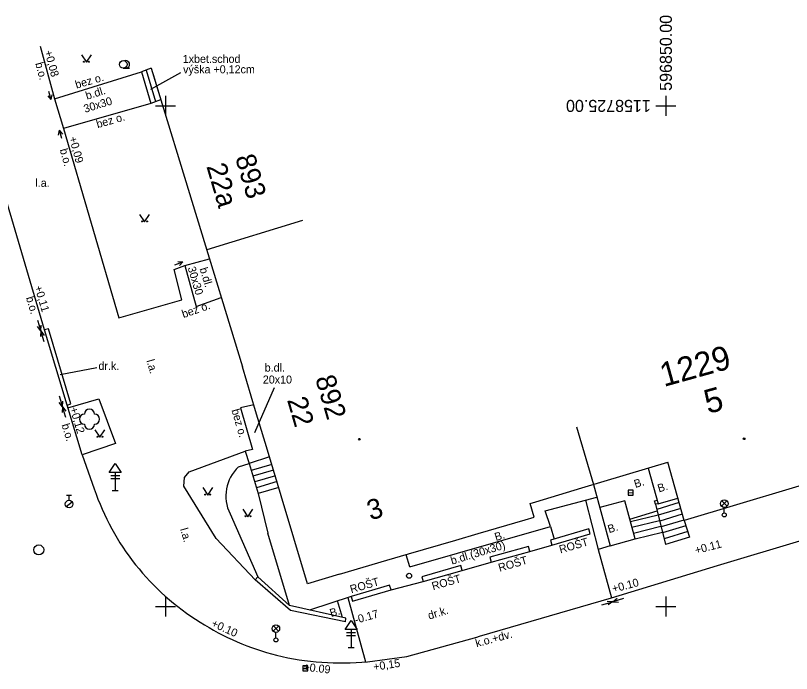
# Model space of a CAD drawing. Extents: x -597333 to -596488, y -1158921 to -1158644.
# Drawn here: x -596882.49 to -596843.72, y -1158753.34 to -1158720.49 of the extents above; entities that cross this region are included whole.
import ezdxf

# ---------------------------------------------------------------- set-up
doc = ezdxf.new("R2010")
doc.units = 0
for name, color, linetype in [('Vrstva 12', 7, 'Continuous'), ('Vrstva 14', 7, 'Continuous'), ('Vrstva 15', 7, 'Continuous'), ('Vrstva 17', 7, 'Continuous'), ('Vrstva 22', 7, 'Continuous'), ('Vrstva 23', 7, 'Continuous'), ('Vrstva 24', 7, 'Continuous'), ('Vrstva 25', 7, 'Continuous'), ('Vrstva 29', 7, 'Continuous'), ('Vrstva 4', 7, 'Continuous'), ('Vrstva 41', 7, 'Continuous'), ('Vrstva 43', 7, 'Continuous'), ('Vrstva 44', 7, 'Continuous'), ('Vrstva 49', 7, 'Continuous'), ('Vrstva 5', 7, 'Continuous'), ('Vrstva 50', 7, 'Continuous'), ('Vrstva 52', 7, 'Continuous'), ('Vrstva 62', 7, 'Continuous'), ('Vrstva 7', 7, 'Continuous')]:
    doc.layers.add(name, color=color, linetype=linetype)

msp = doc.modelspace()

# ---------------------------------------------------------------- linework, layer by layer
at = {"layer": 'Vrstva 12'}
msp.add_line((-596853.61, -1158743.9), (-596852.79, -1158746.96), dxfattribs=at)
at = {"layer": 'Vrstva 14'}
msp.add_line((-596877.11, -1158723.117), (-596876.797, -1158723.117), dxfattribs=at)
for points in [[(-596879.2, -1158722.45), (-596878.95, -1158722.825), (-596878.7, -1158722.45)], [(-596876.293, -1158730.419), (-596876.043, -1158730.794), (-596875.793, -1158730.419)], [(-596878.526, -1158741.168), (-596878.276, -1158741.543), (-596878.026, -1158741.168)], [(-596873.141, -1158744.054), (-596872.891, -1158744.429), (-596872.641, -1158744.054)], [(-596871.131, -1158745.135), (-596870.881, -1158745.51), (-596870.631, -1158745.135)]]:
    msp.add_lwpolyline(points, dxfattribs=at)
for centre, radius in [((-596879.075, -1158722.8), 0.025), ((-596878.825, -1158722.8), 0.025), ((-596877.11, -1158722.93), 0.188), ((-596876.168, -1158730.769), 0.025), ((-596875.918, -1158730.769), 0.025), ((-596878.8, -1158740.64), 0.00025), ((-596878.401, -1158741.518), 0.025), ((-596878.151, -1158741.518), 0.025), ((-596873.016, -1158744.404), 0.025), ((-596872.766, -1158744.404), 0.025), ((-596871.006, -1158745.485), 0.025), ((-596870.756, -1158745.485), 0.025)]:
    msp.add_circle(centre, radius, dxfattribs=at)
for centre, radius, start, end in [((-596876.985, -1158722.93), 0.188, 249.4944, 109.0474), ((-596878.8, -1158740.39), 0.25, 0, 180), ((-596879.05, -1158740.64), 0.25, 90, 270), ((-596878.55, -1158740.64), 0.25, 270, 90), ((-596878.8, -1158740.89), 0.25, 180, 360)]:
    msp.add_arc(centre, radius, start, end, dxfattribs=at)
at = {"layer": 'Vrstva 15'}
for p, q in [((-596849.34, -1158744.809), (-596850.451, -1158745.149)), ((-596850.39, -1158744.86), (-596849.403, -1158744.583)), ((-596851.801, -1158745.641), (-596850.436, -1158745.213)), ((-596849.259, -1158745.098), (-596850.38, -1158745.441)), ((-596851.772, -1158745.75), (-596850.387, -1158745.41)), ((-596851.695, -1158746.04), (-596850.316, -1158745.701)), ((-596849.178, -1158745.387), (-596850.308, -1158745.733)), ((-596849.097, -1158745.676), (-596850.236, -1158746.024)), ((-596849.09, -1158745.7), (-596848.81, -1158746.53)), ((-596851.618, -1158746.329), (-596850.244, -1158745.991)), ((-596849.002, -1158745.961), (-596850.164, -1158746.316)), ((-596851.54, -1158746.62), (-596850.172, -1158746.283)), ((-596848.906, -1158746.246), (-596850.092, -1158746.608)), ((-596848.81, -1158746.53), (-596850.02, -1158746.9))]:
    msp.add_line(p, q, dxfattribs=at)
for centre in [(-596865.317, -1158741.643), (-596846.092, -1158741.617)]:
    msp.add_circle(centre, 0.0438, dxfattribs=at)
at = {"layer": 'Vrstva 17'}
for p, q in [((-596870.394, -1158748.51), (-596870.526, -1158748.667)), ((-596868.763, -1158750.198), (-596870.526, -1158748.667)), ((-596868.81, -1158749.945), (-596870.394, -1158748.51)), ((-596865.986, -1158750.584), (-596868.81, -1158749.945)), ((-596866.004, -1158750.767), (-596868.763, -1158750.198)), ((-596866.004, -1158750.767), (-596865.986, -1158750.584))]:
    msp.add_line(p, q, dxfattribs=at)
at = {"layer": 'Vrstva 22'}
for p, q in [((-596850.878, -1158743.083), (-596850.39, -1158744.86)), ((-596851.54, -1158746.62), (-596852.05, -1158744.71)), ((-596850.39, -1158744.86), (-596850.515, -1158744.891)), ((-596850.515, -1158744.891), (-596850.02, -1158746.9))]:
    msp.add_line(p, q, dxfattribs=at)
at = {"layer": 'Vrstva 23'}
msp.add_circle((-596862.83, -1158748.46), 0.125, dxfattribs=at)
at = {"layer": 'Vrstva 24'}
for p, q in [((-596879.944, -1158744.44), (-596879.694, -1158744.44)), ((-596879.819, -1158744.69), (-596879.819, -1158744.44)), ((-596879.966, -1158744.994), (-596879.671, -1158744.762))]:
    msp.add_line(p, q, dxfattribs=at)
msp.add_circle((-596879.819, -1158744.878), 0.188, dxfattribs=at)
at = {"layer": 'Vrstva 25'}
for p, q in [((-596851.885, -1158744.309), (-596851.635, -1158744.311)), ((-596868.134, -1158753.085), (-596867.884, -1158753.085))]:
    msp.add_line(p, q, dxfattribs=at)
for points in [[(-596851.884, -1158744.436), (-596851.634, -1158744.434), (-596851.636, -1158744.184), (-596851.886, -1158744.186)], [(-596868.134, -1158753.21), (-596867.884, -1158753.21), (-596867.884, -1158752.96), (-596868.134, -1158752.96)]]:
    msp.add_lwpolyline(points, close=True, dxfattribs=at)
msp.add_circle((-596881.332, -1158747.168), 0.25, dxfattribs=at)
at = {"layer": 'Vrstva 29'}
for p, q in [((-596847.212, -1158744.989), (-596846.948, -1158744.725)), ((-596846.944, -1158744.988), (-596847.208, -1158744.723)), ((-596847.08, -1158745.32), (-596847.08, -1158745.045)), ((-596869.616, -1158751.232), (-596869.352, -1158750.968)), ((-596869.348, -1158751.231), (-596869.612, -1158750.966)), ((-596869.484, -1158751.563), (-596869.484, -1158751.288))]:
    msp.add_line(p, q, dxfattribs=at)
for centre, radius in [((-596847.08, -1158744.857), 0.188), ((-596847.08, -1158745.42), 0.1), ((-596869.484, -1158751.1), 0.188), ((-596869.484, -1158751.663), 0.1)]:
    msp.add_circle(centre, radius, dxfattribs=at)
at = {"layer": 'Vrstva 4'}
for p, q in [((-596875.72, -1158723.11), (-596871.154, -1158738.036)), ((-596875.484, -1158724.792), (-596875.955, -1158723.23)), ((-596868.16, -1158730.73), (-596872.942, -1158732.192)), ((-596870.504, -1158740.22), (-596871.154, -1158738.036)), ((-596854.47, -1158741.026), (-596853.61, -1158743.9)), ((-596867.913, -1158748.855), (-596869.897, -1158742.184)), ((-596869.799, -1158742.515), (-596870.815, -1158742.849)), ((-596870.815, -1158742.849), (-596870.376, -1158744.35)), ((-596869.685, -1158742.897), (-596870.713, -1158743.198)), ((-596869.599, -1158743.185), (-596870.629, -1158743.486)), ((-596869.511, -1158743.472), (-596870.544, -1158743.774)), ((-596869.428, -1158743.76), (-596870.46, -1158744.062)), ((-596869.343, -1158744.048), (-596870.376, -1158744.35)), ((-596866.299, -1158748.381), (-596867.913, -1158748.855))]:
    msp.add_line(p, q, dxfattribs=at)
for points in [[(-596875.72, -1158723.11), (-596876.2, -1158723.3), (-596875.727, -1158724.883)], [(-596875.247, -1158724.703), (-596875.727, -1158724.883)], [(-596854.196, -1158744.075), (-596849.905, -1158742.792)], [(-596841.08, -1158743.3), (-596849.09, -1158745.7), (-596849.905, -1158742.792)], [(-596857.032, -1158745.672), (-596856.58, -1158745.54), (-596856.782, -1158744.849), (-596856.503, -1158744.766)], [(-596860.493, -1158746.682), (-596859.376, -1158746.356)], [(-596863.933, -1158747.686), (-596862.859, -1158747.372)]]:
    msp.add_lwpolyline(points, dxfattribs=at)
at = {"layer": 'Vrstva 41'}
for p, q in [((-596871.352, -1158743.026), (-596870.815, -1158742.849)), ((-596871.777, -1158745.363), (-596870.394, -1158748.51))]:
    msp.add_line(p, q, dxfattribs=at)
msp.add_arc((-596870.001, -1158744.479), 1.984, 132.92, 206.466, dxfattribs=at)
at = {"layer": 'Vrstva 44'}
for p, q in [((-596877.512, -1158743.306), (-596877.512, -1158744.206)), ((-596877.732, -1158743.456), (-596877.284, -1158743.456)), ((-596877.732, -1158743.606), (-596877.289, -1158743.606)), ((-596877.662, -1158744.206), (-596877.362, -1158744.206)), ((-596865.951, -1158751.288), (-596865.503, -1158751.288)), ((-596865.951, -1158751.438), (-596865.508, -1158751.438)), ((-596865.731, -1158751.138), (-596865.731, -1158752.038)), ((-596865.881, -1158752.038), (-596865.581, -1158752.038))]:
    msp.add_line(p, q, dxfattribs=at)
for points in [[(-596877.812, -1158743.311), (-596877.512, -1158742.856), (-596877.212, -1158743.311)], [(-596866.031, -1158751.143), (-596865.731, -1158750.688), (-596865.431, -1158751.143)]]:
    msp.add_lwpolyline(points, close=True, dxfattribs=at)
at = {"layer": 'Vrstva 49'}
for p, q in [((-596875.73, -1158724.16), (-596874.234, -1158723.332)), ((-596880.886, -1158724.497), (-596880.724, -1158724.687)), ((-596880.683, -1158724.44), (-596880.724, -1158724.687)), ((-596880.34, -1158726.462), (-596880.298, -1158726.216)), ((-596880.136, -1158726.406), (-596880.298, -1158726.216)), ((-596874.38, -1158732.766), (-596874.131, -1158732.783)), ((-596874.304, -1158732.963), (-596874.131, -1158732.783)), ((-596881.389, -1158735.694), (-596881.225, -1158736.233)), ((-596881.227, -1158736.233), (-596881.214, -1158735.95)), ((-596881.223, -1158736.236), (-596881.394, -1158736.011)), ((-596881.227, -1158736.233), (-596881.239, -1158736.515)), ((-596881.063, -1158736.772), (-596881.227, -1158736.233)), ((-596881.227, -1158736.233), (-596881.056, -1158736.457)), ((-596880.269, -1158738.417), (-596878.432, -1158738.059)), ((-596869.569, -1158739.076), (-596870.556, -1158741.316)), ((-596880.311, -1158739.484), (-596880.147, -1158740.024)), ((-596880.145, -1158740.026), (-596880.315, -1158739.802)), ((-596880.148, -1158740.023), (-596880.135, -1158739.741)), ((-596880.148, -1158740.023), (-596880.161, -1158740.306)), ((-596879.984, -1158740.563), (-596880.148, -1158740.023)), ((-596880.148, -1158740.023), (-596879.978, -1158740.248)), ((-596853.193, -1158749.912), (-596852.651, -1158749.753)), ((-596852.652, -1158749.754), (-596852.934, -1158749.738)), ((-596852.649, -1158749.751), (-596852.876, -1158749.918)), ((-596852.652, -1158749.754), (-596852.426, -1158749.586)), ((-596852.111, -1158749.596), (-596852.652, -1158749.754)), ((-596852.652, -1158749.754), (-596852.371, -1158749.77))]:
    msp.add_line(p, q, dxfattribs=at)
for points in [[(-596880.84, -1158724.268), (-596880.724, -1158724.687)], [(-596880.182, -1158726.634), (-596880.298, -1158726.216)], [(-596874.536, -1158732.939), (-596874.131, -1158732.783)]]:
    msp.add_lwpolyline(points, dxfattribs=at)
at = {"layer": 'Vrstva 5'}
for p, q in [((-596875.619, -1158723.44), (-596875.338, -1158724.359)), ((-596869.897, -1158742.184), (-596870.504, -1158740.22)), ((-596856.503, -1158744.766), (-596854.196, -1158744.075)), ((-596859.376, -1158746.356), (-596857.032, -1158745.672)), ((-596862.859, -1158747.372), (-596860.493, -1158746.682)), ((-596866.3, -1158748.376), (-596863.933, -1158747.685))]:
    msp.add_line(p, q, dxfattribs=at)
at = {"layer": 'Vrstva 62'}
for p, q in [((-596875, -1158724.5), (-596875, -1158725.5)), ((-596850, -1158724.5), (-596850, -1158725.5)), ((-596875.5, -1158725), (-596874.5, -1158725)), ((-596850.5, -1158725), (-596849.5, -1158725)), ((-596875, -1158749.5), (-596875, -1158750.5)), ((-596850, -1158749.5), (-596850, -1158750.5)), ((-596875.5, -1158750), (-596874.5, -1158750)), ((-596850.5, -1158750), (-596849.5, -1158750))]:
    msp.add_line(p, q, dxfattribs=at)
at = {"layer": 'Vrstva 7'}
for p, q in [((-596880.55, -1158724.65), (-596880.1, -1158726.13)), ((-596879.16, -1158742.42), (-596878.562, -1158744.124)), ((-596873.817, -1158743.267), (-596871.015, -1158742.241)), ((-596871.015, -1158742.241), (-596870.815, -1158742.849)), ((-596874.049, -1158743.546), (-596873.817, -1158743.267)), ((-596874.09, -1158743.993), (-596874.049, -1158743.546)), ((-596872.476, -1158746.598), (-596874.09, -1158743.993)), ((-596870.376, -1158744.35), (-596869.893, -1158746.333)), ((-596856.03, -1158745.21), (-596853.442, -1158744.528)), ((-596854.02, -1158744.68), (-596853.38, -1158747.14)), ((-596852.05, -1158744.71), (-596853.303, -1158745.046)), ((-596850.56, -1158744.71), (-596850.44, -1158744.677)), ((-596850.515, -1158744.891), (-596850.56, -1158744.71)), ((-596855.77, -1158746), (-596856.03, -1158745.21)), ((-596862.8, -1158748.02), (-596855.77, -1158746)), ((-596855.77, -1158746), (-596855.583, -1158746.632)), ((-596868.81, -1158749.945), (-596869.893, -1158746.333)), ((-596870.526, -1158748.667), (-596872.476, -1158746.598)), ((-596852.79, -1158746.96), (-596851.54, -1158746.62)), ((-596856.8, -1158747.24), (-596855.7, -1158746.93)), ((-596852.79, -1158746.96), (-596853.38, -1158747.14)), ((-596853.38, -1158747.14), (-596852.71, -1158749.56)), ((-596862.8, -1158748.02), (-596862.979, -1158747.407)), ((-596860.17, -1158748.19), (-596858.73, -1158747.78)), ((-596863.73, -1158749.17), (-596862.12, -1158748.75)), ((-596865.73, -1158749.49), (-596867.807, -1158750.172)), ((-596865.895, -1158749.544), (-596865.004, -1158752.763)), ((-596866.156, -1158750.545), (-596866.4, -1158749.71)), ((-596862.945, -1158752.483), (-596859.436, -1158751.525)), ((-596864.91, -1158752.755), (-596862.945, -1158752.483))]:
    msp.add_line(p, q, dxfattribs=at)
for points in [[(-596881.27, -1158722.02), (-596880.55, -1158724.65), (-596876.2, -1158723.3)], [(-596879.16, -1158742.42), (-596879.92, -1158739.94), (-596881.04, -1158736.18), (-596883.32, -1158728.49), (-596884.3, -1158722.75)], [(-596875.727, -1158724.883), (-596880.1, -1158726.13), (-596877.33, -1158735.58), (-596874.18, -1158734.69), (-596874.56, -1158733.17), (-596874.04, -1158732.97), (-596872.807, -1158732.634)], [(-596874.04, -1158732.97), (-596873.47, -1158735.01), (-596872.213, -1158734.573)], [(-596879.92, -1158739.94), (-596879.729, -1158739.882), (-596880.848, -1158736.123), (-596881.04, -1158736.18)], [(-596879.876, -1158740.083), (-596878.33, -1158739.62), (-596877.5, -1158741.86), (-596879.16, -1158742.42)], [(-596870.592, -1158739.925), (-596871.25, -1158740.07), (-596870.65, -1158742.16), (-596871.015, -1158742.241)], [(-596859.436, -1158751.525), (-596859.31, -1158751.47), (-596852.71, -1158749.56), (-596847.42, -1158747.94), (-596838.86, -1158745.39)]]:
    msp.add_lwpolyline(points, dxfattribs=at)
for points in [[(-596855.7, -1158746.93), (-596853.78, -1158746.36), (-596853.851, -1158746.12), (-596855.771, -1158746.69)], [(-596858.73, -1158747.78), (-596856.8, -1158747.24), (-596856.867, -1158746.999), (-596858.797, -1158747.539)], [(-596862.12, -1158748.75), (-596860.17, -1158748.19), (-596860.239, -1158747.95), (-596862.189, -1158748.51)], [(-596865.659, -1158749.733), (-596863.73, -1158749.17), (-596863.8, -1158748.93), (-596865.729, -1158749.493)]]:
    msp.add_lwpolyline(points, close=True, dxfattribs=at)
for centre, radius, start, end in [((-596866.616, -1158740.05), 12.622, 198.8311, 238.1881), ((-596866.258, -1158739.804), 13.021, 237.4205, 255.7988), ((-596866.196, -1158738.947), 13.867, 256.4193, 275.3198)]:
    msp.add_arc(centre, radius, start, end, dxfattribs=at)

# ---------------------------------------------------------------- texts
at = {"layer": 'Vrstva 43'}
for s, height, rotation, p in [('893', 1, 286.3012, (-596871.527, -1158727.573)), ('22a', 1, 286.3012, (-596872.964, -1158728.013)), ('1229', 1.2, 15.5254, (-596850.101, -1158739.036)), ('892', 1, 286.3012, (-596867.529, -1158738.598)), ('5', 1.2, 15.5254, (-596847.895, -1158740.388)), ('22', 1, 286.3012, (-596868.933, -1158739.676)), ('3', 1, 17.2228, (-596864.755, -1158745.704))]:
    msp.add_text(s, height=height, rotation=rotation, dxfattribs=at).set_placement(p)
at = {"layer": 'Vrstva 49'}
for s, p in [('1xbet.schod', (-596874.139, -1158722.853)), ('l.a.', (-596881.502, -1158729.041)), ('dr.k.', (-596878.35, -1158738.179)), ('b.dl.', (-596870.044, -1158738.266)), ('20x10', (-596870.137, -1158738.863))]:
    msp.add_text(s, height=0.4, dxfattribs=at).set_placement(p)
for s, rotation, p in [('b.o.', 285.3104, (-596881.514, -1158722.88)), ('bez o.', 15.9106, (-596879.451, -1158724.141)), ('b.dl.', 17.2415, (-596878.925, -1158724.695)), ('30x30', 17.2415, (-596879.019, -1158725.35)), ('bez o.', 15.9106, (-596878.394, -1158726.116)), ('b.o.', 285.3104, (-596880.286, -1158727.187)), ('30x30', 286.534, (-596873.898, -1158733.083)), ('b.dl.', 286.534, (-596873.3, -1158733.13)), ('b.o.', 286.5145, (-596881.977, -1158734.576)), ('bez o.', 19.179, (-596874.104, -1158735.6)), ('l.a.', 286.3885, (-596875.959, -1158737.72)), ('bez o.', 286.0178, (-596871.705, -1158740.19)), ('b.o.', 286.5145, (-596880.194, -1158740.923)), ('B.', 17.0425, (-596851.522, -1158744.079)), ('B.', 17.0425, (-596850.345, -1158744.3)), ('l.a.', 286.3885, (-596874.274, -1158746.132)), ('B.', 17.0425, (-596852.836, -1158746.335)), ('B.', 17.0425, (-596858.488, -1158746.727)), ('b.dl.(30x30)', 16.7748, (-596860.687, -1158747.907)), ('ROŠT', 16.1951, (-596855.267, -1158747.349)), ('ROŠT', 16.1951, (-596858.305, -1158748.262)), ('ROŠT', 16.1951, (-596861.629, -1158749.183)), ('ROŠT', 16.1951, (-596865.718, -1158749.335)), ('B.', 17.0425, (-596866.725, -1158750.524)), ('dr.k.', 17.3144, (-596861.82, -1158750.652)), ('k.o.+dv.', 15, (-596859.456, -1158752.029))]:
    msp.add_text(s, height=0.4, rotation=rotation, dxfattribs=at).set_placement(p)
at = {"layer": 'Vrstva 50'}
for s, rotation, p in [('+0,08', 285.3104, (-596881.056, -1158722.28)), ('+0,09', 285.3104, (-596879.828, -1158726.588)), ('+0,11', 286.5145, (-596881.554, -1158734.031)), ('+0,12', 286.5145, (-596879.789, -1158740.099)), ('+0.11', 14.7779, (-596848.492, -1158747.385)), ('+0.10', 14.7779, (-596852.627, -1158749.308)), ('-0.17', 15.9978, (-596865.492, -1158750.864)), ('+0.10', 335.5003, (-596872.745, -1158750.971)), ('+0,15', 8.7992, (-596864.586, -1158753.209)), ('+0.09', 353.8901, (-596868.126, -1158753.198))]:
    msp.add_text(s, height=0.4, rotation=rotation, dxfattribs=at).set_placement(p)
msp.add_text('výška +0,12cm', height=0.4, dxfattribs=at).set_placement((-596874.12, -1158723.374))
at = {"layer": 'Vrstva 52'}
for s, rotation, p in [('596850.00', 90, (-596849.7, -1158724.25)), ('1158725.00', 180, (-596850.75, -1158724.7))]:
    msp.add_text(s, height=0.6, rotation=rotation, dxfattribs=at).set_placement(p)

doc.saveas('drawing.dxf')
